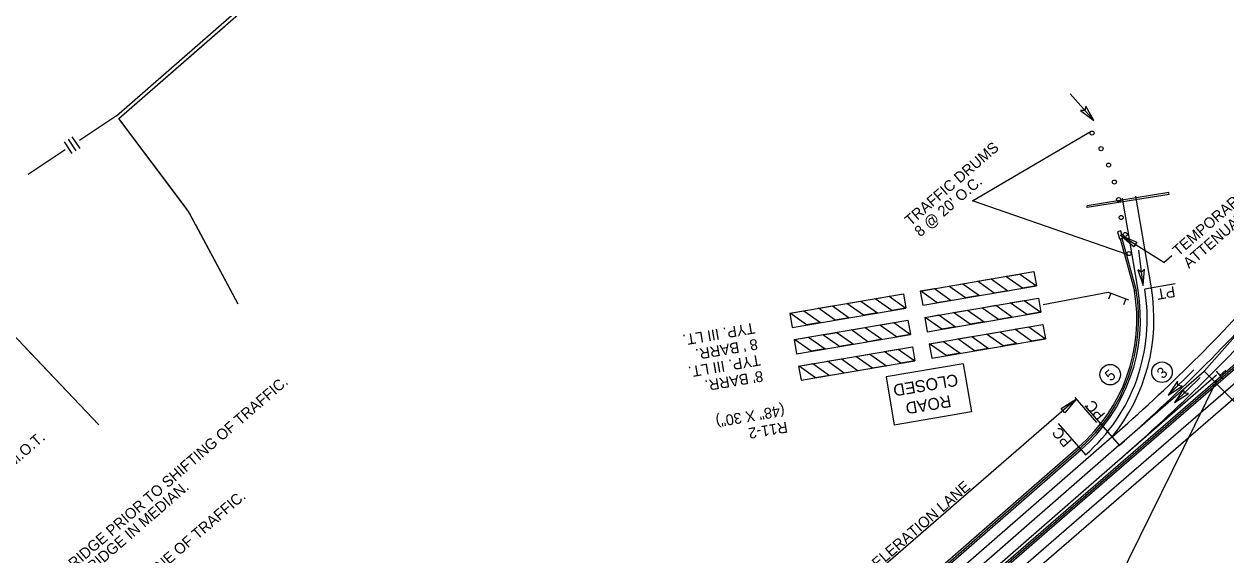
# Model space of a CAD drawing. Extents: x 259983 to 267998, y 211467 to 219827.
# Drawn here: x 263924 to 265258, y 214157 to 214746 of the extents above; entities that cross this region are included whole.
import ezdxf

# ---------------------------------------------------------------- set-up
doc = ezdxf.new("R2010")
doc.units = 0
for name, color, linetype in [('1', 7, 'Continuous'), ('DRAINAGE', 7, 'Continuous'), ('Level 24', 7, 'Continuous'), ('Level 43', 7, 'Continuous'), ('Level 58', 7, 'Continuous'), ('R-W - CofA', 7, 'Continuous'), ('R_MOT', 7, 'Continuous'), ('R_MOT STAGE 1', 7, 'Continuous'), ('R_MOT STAGE 2', 7, 'Continuous'), ('ROAD', 7, 'Continuous')]:
    doc.layers.add(name, color=color, linetype=linetype)

msp = doc.modelspace()

# ---------------------------------------------------------------- linework, layer by layer
at = {"layer": '1'}
for p, q in [((265189.4, 214481.5), (265198.3, 214489.2)), ((265247.9, 214350.2), (265087.5, 214024.3))]:
    msp.add_line(p, q, dxfattribs=at)
for points in [[(265156.3, 214498.9), (265141.1, 214511.9), (265159.5, 214504)], [(265075.6, 214319.3), (265092.5, 214330), (265079.5, 214314.7)]]:
    msp.add_lwpolyline(points, close=True, dxfattribs=at)
at = {"layer": 'DRAINAGE'}
for p, q in [((265195.1, 214559), (265104.2, 214544.5)), ((265195.4, 214557), (265104.5, 214542.5))]:
    msp.add_line(p, q, dxfattribs=at)
for points in [[(265195.4, 214557), (265195.1, 214559)], [(265104.5, 214542.5), (265104.2, 214544.5)]]:
    msp.add_lwpolyline(points, dxfattribs=at)
at = {"layer": 'Level 43'}
for points in [[(265111.9, 214639.1), (265085.5, 214668.8)], [(265166.5, 214455.8), (265161.7, 214495.2)], [(265194.3, 214334.4), (265222.7, 214362.2)], [(265201.4, 214326.1), (265229.7, 214353.9)]]:
    msp.add_lwpolyline(points, dxfattribs=at)
at = {"layer": 'Level 58'}
for points in [[(265097.1, 214650.1), (265111.9, 214639.1), (265102.7, 214655), (265101.9, 214650.3)], [(265160.6, 214473.2), (265166.5, 214455.8), (265168, 214474.1), (265164.7, 214470.7)], [(265204.5, 214349.7), (265194.3, 214334.4), (265209.8, 214344.3), (265205, 214344.9)], [(265211.6, 214341.4), (265201.4, 214326.1), (265216.8, 214336), (265212.1, 214336.6)]]:
    msp.add_lwpolyline(points, close=True, dxfattribs=at)
at = {"layer": 'R-W - CofA'}
for p, q in [((264026.6, 214644.4), (263985.4, 214617)), ((263977.4, 214602.4), (263968.8, 214615.4)), ((263981.8, 214605.2), (263973.1, 214618.2)), ((263986.1, 214608.1), (263977.5, 214621.1)), ((263969.5, 214606.5), (263928.4, 214579.1))]:
    msp.add_line(p, q, dxfattribs=at)
for points in [[(264029.2, 214641.4), (264982.3, 215471.9)], [(264026.6, 214644.4), (264282.1, 214867.1)], [(264029.2, 214641.4), (264146.7, 214743.8)], [(264104.3, 214541.4), (264029.2, 214641.4)], [(264161.6, 214435.3), (264106.7, 214538.2), (264029.2, 214641.4)], [(264108.8, 214534.2), (264106.7, 214538.2), (264106.6, 214538.3)], [(264112.8, 214526.7), (264110.6, 214530.8)], [(264161.6, 214435.3), (264114.6, 214523.3)], [(263840.2, 214476.7), (264006.8, 214301.3)], [(263924.3, 214388.2), (263927.4, 214384.9)], [(263930.1, 214382.1), (263933.2, 214378.8)], [(263935.8, 214376), (264006.8, 214301.3)]]:
    msp.add_lwpolyline(points, dxfattribs=at)
at = {"layer": 'R_MOT'}
for p, q in [((264919, 214449.8), (265045.3, 214471.3)), ((265045.3, 214471.3), (265048, 214455.5)), ((264919, 214449.8), (264921.7, 214434)), ((264921.7, 214434), (265048, 214455.5)), ((264774.1, 214425.2), (264900.3, 214446.7)), ((264900.3, 214446.7), (264903, 214430.8)), ((264924, 214420.5), (265050.3, 214442)), ((265050.3, 214442), (265053, 214426.2)), ((265050.3, 214442), (265053, 214426.2)), ((265127.6, 214448.7), (265150.4, 214440)), ((265130.5, 214447.6), (265127.9, 214440.7)), ((265147.3, 214441.2), (265144.7, 214434.3)), ((264774.1, 214425.2), (264776.8, 214409.4)), ((264776.8, 214409.4), (264903, 214430.8)), ((264926.7, 214404.7), (265053, 214426.2)), ((264779, 214395.9), (264905.3, 214417.4)), ((264905.3, 214417.4), (264908, 214401.6)), ((264905.3, 214417.4), (264908, 214401.6)), ((264924, 214420.5), (264926.7, 214404.7)), ((264929, 214391.2), (265055.3, 214412.7)), ((265055.2, 214412.6), (265055.3, 214412.5)), ((265055.3, 214412.7), (265058, 214396.8)), ((264779, 214395.9), (264781.7, 214380.1)), ((264781.7, 214380.1), (264908, 214401.6)), ((264931.7, 214375.4), (265058, 214396.8)), ((264784, 214366.5), (264910.3, 214388)), ((264910.2, 214388), (264910.3, 214387.9)), ((264910.3, 214388), (264913, 214372.2)), ((264929, 214391.2), (264931.7, 214375.4)), ((264786.7, 214350.7), (264913, 214372.2)), ((264966.8, 214369.1), (264881.1, 214354.5)), ((264966.8, 214369.1), (264975.9, 214315.6)), ((264784, 214366.5), (264786.7, 214350.7)), ((265255.9, 214351.8), (265247.9, 214361)), ((265251.9, 214356.4), (265258.4, 214362)), ((264881.1, 214354.5), (264890.2, 214301)), ((264975.9, 214315.6), (264890.2, 214301))]:
    msp.add_line(p, q, dxfattribs=at)
for points in [[(265016.4, 214450.1), (265000.9, 214447.6), (264982.5, 214460.6), (264997.9, 214463.3)], [(265048, 214455.5), (265032.5, 214452.9), (265014, 214466), (265029.5, 214468.6)], [(264953.3, 214439.4), (264937.8, 214436.8), (264919.4, 214449.9), (264934.8, 214452.5)], [(264984.9, 214444.8), (264969.4, 214442.2), (264950.9, 214455.3), (264966.4, 214457.9)], [(264871.5, 214425.5), (264855.9, 214422.9), (264837.5, 214436), (264853, 214438.6)], [(264903, 214430.8), (264887.5, 214428.3), (264869, 214441.3), (264884.5, 214444)], [(265053, 214426.2), (265037.4, 214423.6), (265019, 214436.7), (265034.5, 214439.3)], [(264808.4, 214414.7), (264792.8, 214412.2), (264774.4, 214425.2), (264789.9, 214427.9)], [(264839.9, 214420.1), (264824.4, 214417.5), (264805.9, 214430.6), (264821.4, 214433.2)], [(264958.3, 214410.1), (264942.8, 214407.5), (264924.4, 214420.6), (264939.8, 214423.2)], [(264989.9, 214415.5), (264974.3, 214412.9), (264955.9, 214426), (264971.4, 214428.6)], [(265021.4, 214420.9), (265005.9, 214418.3), (264987.5, 214431.3), (265002.9, 214434)], [(264876.4, 214396.2), (264860.9, 214393.6), (264842.5, 214406.7), (264857.9, 214409.3)], [(264908, 214401.6), (264892.5, 214399), (264874, 214412), (264889.5, 214414.7)], [(265058, 214396.8), (265042.4, 214394.2), (265024, 214407.3), (265039.5, 214410)], [(264813.3, 214385.5), (264797.8, 214382.9), (264779.4, 214395.9), (264794.9, 214398.6)], [(264844.9, 214390.8), (264829.4, 214388.2), (264810.9, 214401.3), (264826.4, 214403.9)], [(264994.9, 214386.1), (264979.3, 214383.5), (264960.9, 214396.6), (264976.4, 214399.2)], [(265026.4, 214391.5), (265010.9, 214388.9), (264992.5, 214402), (265007.9, 214404.6)], [(264913, 214372.2), (264897.5, 214369.6), (264879, 214382.7), (264894.5, 214385.3)], [(264963.3, 214380.7), (264947.8, 214378.1), (264929.4, 214391.2), (264944.8, 214393.8)], [(264818.3, 214356.1), (264802.8, 214353.5), (264784.4, 214366.6), (264799.9, 214369.2)], [(264849.9, 214361.4), (264834.4, 214358.8), (264815.9, 214371.9), (264831.4, 214374.6)], [(264881.4, 214366.8), (264865.9, 214364.2), (264847.5, 214377.3), (264862.9, 214379.9)]]:
    msp.add_lwpolyline(points, close=True, dxfattribs=at)
at = {"layer": 'R_MOT STAGE 1'}
for p, q in [((265160.8, 214450.8), (265143.6, 214552.7)), ((265175.6, 214453.3), (265158.4, 214555.2)), ((265141.1, 214507.8), (265143, 214508.3)), ((265141.1, 214507.8), (265156.9, 214449.9)), ((265143, 214508.3), (265158.9, 214450.4)), ((265201.9, 214457.7), (265168.2, 214452)), ((265317, 214454.7), (265234.2, 214360.8)), ((263990.3, 213262.5), (265310, 214405)), ((263991.6, 213261), (265311.3, 214403.5)), ((265093.3, 214212.1), (265312.6, 214402)), ((265101.2, 214203), (265320.6, 214393)), ((265109, 214194), (265328.6, 214384.1)), ((264720.4, 213897.2), (265247.8, 214356.8)), ((265139.8, 214278.6), (265234.2, 214360.8)), ((265281, 214313.6), (265234.2, 214360.8)), ((265101.7, 214322.3), (265139.8, 214278.6)), ((265072.1, 214302.7), (265102.4, 214267.9)), ((265094.9, 214276.6), (264711.1, 213942.2)), ((265139.8, 214278.6), (264712.5, 213906.3)), ((265131.9, 214287.6), (264949.3, 214128.5)), ((265140, 214278.7), (265139.8, 214278.6)), ((265096.2, 214275.1), (264712.4, 213940.7)), ((265097.5, 214273.5), (264713.7, 213939.2)), ((263992.9, 213259.5), (265093.3, 214212.1)), ((264796, 213938.9), (265101.2, 214203)), ((265005.2, 214104.1), (265108.7, 214193.7)), ((265108.7, 214193.7), (265109, 214194))]:
    msp.add_line(p, q, dxfattribs=at)
msp.add_lwpolyline([(265138.1, 214515.6), (265140.3, 214507.6), (265143.9, 214508.6), (265141.7, 214516.6)], close=True, dxfattribs=at)
for centre, radius in [((265109.8, 214625.1), 2.25), ((265119.8, 214607.8), 2.25), ((265128.1, 214589.6), 2.25), ((265134.6, 214570.7), 2.25), ((265139.3, 214551.2), 2.25), ((265142.1, 214531.4), 2.25), ((265146.6, 214512.6), 2.25), ((265150.9, 214491.4), 2.25), ((265187.5, 214359.7), 11.4), ((265129.9, 214357), 11.4)]:
    msp.add_circle(centre, radius, dxfattribs=at)
for centre, radius, start, end in [((263885.1, 215718.5), 1897.9, 311.0667, 318.5667), ((264971, 214418.7), 188.5, 311.0667, 9.5976), ((264971, 214418.7), 190.5, 311.0667, 9.5976), ((264971, 214418.7), 192.5, 311.0648, 9.5976), ((264971, 214418.7), 200, 311.0648, 9.5976), ((264971, 214418.7), 207.5, 320.8318, 9.5976), ((263885.1, 215718.5), 1909.9, 311.0667, 318.5667), ((263885.1, 215718.5), 1921.9, 311.0667, 318.5667)]:
    msp.add_arc(centre, radius, start, end, dxfattribs=at)
at = {"layer": 'R_MOT STAGE 2'}
for p, q in [((264977.1, 214549.9), (265108.9, 214627.2)), ((265148.8, 214490.5), (264977.1, 214549.9)), ((265189.4, 214481.5), (265141.1, 214511.9)), ((265055.4, 214434.7), (265127.6, 214448.7)), ((265092.5, 214330), (264682.6, 213975.1)), ((265115, 214304), (265091.2, 214331.5))]:
    msp.add_line(p, q, dxfattribs=at)

# ---------------------------------------------------------------- texts
at = {"layer": '1'}
for s, rotation, p in [('TEMPORARY IMPACT', 40.8733, (265205.7, 214487.9)), ('ATTENUATION BARRIER', 40.8733, (265217.4, 214474.3)), ('5', 40.8733, (265130.4, 214349)), ('3', 40.8733, (265188.1, 214351.7)), ("540' ACCELERATION LANE", 40.8833, (264820.2, 214096.5))]:
    msp.add_text(s, height=12, rotation=rotation, dxfattribs=at).set_placement(p)
at = {"layer": 'Level 24'}
for s, p in [('TRAFFIC DRUMS', (264908.3, 214521.5)), ("8 @ 20' O.C.", (264919, 214509.2))]:
    msp.add_text(s, height=12, rotation=40.8835, dxfattribs=at).set_placement(p)
at = {"layer": 'R_MOT'}
for s, height, p in [('TYP. III LT.', 12, (264734.4, 214414.7)), ("8 ' BARR.", 12, (264737.5, 214396.9)), ('TYP. III LT.', 12, (264740.5, 214379.2)), ("8' BARR.", 12, (264743.5, 214361.4)), ('CLOSED', 13.22, (264959.8, 214357.9)), ('ROAD', 13.15, (264952, 214334.3)), ('(48" X 30")', 12, (264767.5, 214323.3)), ('R11-2', 12, (264770.6, 214304.8))]:
    msp.add_text(s, height=height, rotation=189.6559, dxfattribs=at).set_placement(p)
at = {"layer": 'R_MOT STAGE 1'}
for s, rotation, p in [('PT', 189.5976, (265201, 214455.2)), ('PC', 131.0667, (265125.1, 214313.1)), ('PC', 131.0648, (265088, 214283.2))]:
    msp.add_text(s, height=12, rotation=rotation, dxfattribs=at).set_placement(p)
at = {"layer": 'ROAD'}
for s, p in [('CONSTRUCT PORTION OF APPROACH ON OFF END OF SHELL LAKE BRIDGE PRIOR TO SHIFTING OF TRAFFIC.', (263567, 213783.7)), ('TRENCH AND SHOULDER PREPARATION OF OUTSIDE SHOULDERS FOR M.O.T.', (263481.9, 213882)), ('ROUTE I-40 E.B. TRAFFIC TO NEWLY CONSTRUCTED APPROACH AND BRIDGE IN MEDIAN.', (263577.6, 213771.4)), ('PLACE PORTION OF PAVEMENT TRANSITION ON E.B. LANES UTILIZING ONE LANE OF TRAFFIC.', (263609.6, 213734.5))]:
    msp.add_text(s, height=12, rotation=40.8833, dxfattribs=at).set_placement(p)

doc.saveas('drawing.dxf')
